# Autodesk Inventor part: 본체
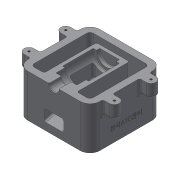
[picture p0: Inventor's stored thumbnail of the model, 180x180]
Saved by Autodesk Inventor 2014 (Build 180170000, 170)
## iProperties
Created: 2018-01
Part Number: 본체
Material: Generic
Document SubType Name: Modeling
Designer: user
Density: 1 g/cm^3
Appearance: Default
Mass: 368.651 g
Surface Area: 834.687 cm^2
Volume: 368.651 cm^3
Author: user
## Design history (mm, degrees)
sketch "Sketch1"
  geometry: L1 (-40, 55)-(40, 55); L2 (55, 40)-(55, -40); L3 (40, -55)-(-40, -55); L4 (-55, -40)-(-55, 40); L5 (40, 45)-(-40, 45); L6 (-45, 40)-(-45, -40); L7 (-40, -45)-(40, -45); L8 (45, -40)-(45, 40); A1 r 15 centre (-40, 40) between (-40, 55) and (-55, 40); A2 r 15 centre (40, 40) between (55, 40) and (40, 55); A3 r 15 centre (40, -40) between (40, -55) and (55, -40); A4 r 15 centre (-40, -40) between (-55, -40) and (-40, -55); A5 r 5 centre (-40, 40) between (-40, 45) and (-45, 40); A6 r 5 centre (40, 40) between (45, 40) and (40, 45); A7 r 5 centre (40, -40) between (40, -45) and (45, -40); A8 r 5 centre (-40, -40) between (-45, -40) and (-40, -45); 1 further point
  constraints: 16 end point, 16 point on circle, 16 tangent, 8 centre point, 6 equal radius, 4 parallel, 2 perpendicular, 1 horizontal, 3 other
  dimensions: "d0" = 110 distance between parallel lines of L3 L1; "d1" = 110 distance between parallel lines of L2 L4; "d2" = 55 distance from line of point (0, 0) L4; "d3" = 55 distance from line of point (0, 0) L1; "d4" = 10 distance between parallel lines of L5 L1; "d5" = 15 radius of A1; "d6" = 5 radius of A5
extrude "Extrusion1" new body sketch "Sketch1" distance "d7" = 65; taper "d8" = 0 deg
sketch "Sketch2"
  geometry: L1 (-65, -35.5)-(-55, -35.5); L2 (-65, -20.5)-(-55, -20.5); L3 (-65, 20.5)-(-55, 20.5); L4 (-65, 35.5)-(-55, 35.5); L5 (-55, 40)-(-55, -40) reference; L6 (-40, -55)-(40, -55) reference; L7 (-55, -35.5)-(-55, -20.5); L8 (-55, 20.5)-(-55, 35.5); A1 r 7.5 centre (-65, -28) between (-65, -20.5) and (-65, -35.5); A2 r 7.5 centre (-65, 28) between (-65, 35.5) and (-65, 20.5); 1 further point
  constraints: 12 end point, 4 point on circle, 4 point on line, 4 tangent, 3 parallel, 2 centre point, 2 collinear, 1 horizontal, 1 vertical alignment
  dimensions: "d9" = 15 diameter of A1; "d10" = 15 diameter of A2; "d11" = 27 distance from line of L6 A1.centre; "d12" = 56 distance of A1.centre A2.centre; "d13" = 10 distance from line of L5 A1.centre
extrude "Extrusion2" join sketch "Sketch2" distance "d14" = 20; taper "d15" = 0 deg
mirror "Mirror1"
sketch "Sketch3"
  geometry: A1 r 7.5 centre (-65, -28) between (-65, -20.5) and (-65, -35.5) reference; A2 r 7.5 centre (-65, 28) between (-65, 35.5) and (-65, 20.5) reference; A3 r 7.5 centre (65, 28) between (65, 20.5) and (65, 35.5) reference; A4 r 7.5 centre (65, -28) between (65, -35.5) and (65, -20.5) reference; 1 further point
hole "Hole1" sketch "Sketch3" at (-65, -28), (-65, 28), (65, 28), (65, -28) diameter "d16" = 3.242; stored, may be unused: countersink angle "d20" = 90 deg, drill point angle "d22" = 118 deg; dims "d17" = 9, "d18" = 4, "d19" = 2, "d21" = 11
sketch "Sketch4"
  geometry: L1 (8.564, 45)-(30, -35); L2 (30, -35)-(65, -35); L3 (0, 45)-(65, 45) reference; L4 (65, 40)-(65, -40) reference; L5 (0, -40)-(0, 40) reference; L6 (0, -55)-(65, -55) reference; L7 (65, -35)-(65, 45); L8 (65, 45)-(8.564, 45); 1 further point
  constraints: 8 end point, 2 collinear, 2 point on line, 1 horizontal
  dimensions: "d23" = 105 deg angle of L3 L1; "d24" = 30 distance from line of L5 L1.end; "d26" = 20 distance between parallel lines of L6 L2
extrude "Extrusion3" join sketch "Sketch4" stored distance "d27" = 50; taper "d28" = 0 deg
sketch "Sketch5"
  geometry: L1 (65, 55)-(65, -30); L2 (65, 45)-(65, -35) reference; L3 (65, 55)-(57.5, 55); L4 (57.5, 55)-(57.5, 36); L5 (57.5, 36)-(49, 36); L6 (49, 36)-(49, 22); L7 (49, 22)-(45, 22); L8 (45, 22)-(45, -25); L9 (45, -25)-(50, -25); L10 (50, -25)-(50, -30); L11 (50, -30)-(65, -30); L12 (0, 55)-(65, 55) reference; 1 further point
  constraints: 20 end point, 7 parallel, 2 collinear, 2 perpendicular, 2 point on line, 1 vertical
  dimensions: "d29" = 7.5 distance of L1.start L3.end; "d30" = 19 distance of L3.end L4.end; "d31" = 14 distance between parallel lines of L7 L5; "d32" = 16 distance between parallel lines of L6 L1; "d33" = 20 distance between parallel lines of L1 L8; "d34" = 47 distance between parallel lines of L9 L7; "d35" = 15 distance between parallel lines of L1 L10; "d36" = 5 distance between parallel lines of L11 L9
revolve "Revolution1" sketch "Sketch5" stored, may be unused: angle "d37" = 90 deg
sketch "Sketch6"
  geometry: L1 (11.061, 55)-(31.157, -20); L2 (31.157, -20)-(65, -20); L3 (65, -20)-(65, 17); L4 (65, 17)-(39.243, 17); L5 (39.243, 17)-(29.061, 55); L6 (30, -35)-(8.564, 45) reference; L7 (0, 55)-(65, 55) reference; L8 (29.061, 55)-(11.061, 55); L9 (45, 22)-(65, 22) reference; L10 (65, 22)-(65, -25) reference; 1 further point
  constraints: 12 end point, 2 collinear, 2 parallel, 2 perpendicular, 2 point on line, 1 horizontal
  dimensions: "d38" = 5 distance between parallel lines of L6 L1; "d39" = 18 distance of L1.start L5.end; "d40" = 37 distance between parallel lines of L2 L4; "d41" = 5 distance between parallel lines of L9 L4
extrude "Extrusion4" cut sketch "Sketch6" stored distance "d42" = 30; taper "d43" = 0 deg
chamfer "Chamfer1" distance "d44" = 1; stored, may be unused: second distance "d45" = 2, angle "d46" = 45 deg
fillet "Fillet4" dims "d50" = 1
fillet "Fillet5" dims "d51" = 3
fillet "Fillet6" dims "d52" = 3
fillet "Fillet7" dims "d53" = 3
sketch "Sketch8"
  geometry: L1 (-15, 0)-(-15, 65) reference; L2 (15.113, 23.602)-(64.887, 23.602); L3 (64.887, 23.602)-(64.887, 16.398); L4 (64.887, 16.398)-(15.113, 16.398); L5 (15.113, 16.398)-(15.113, 23.602); L6 (40, 23.602)-(40, 16.398); L7 (15.113, 20)-(64.887, 20); 1 further point
  constraints: 4 end point, 4 midpoint, 2 other
  dimensions: "d57" = 55 distance between parallel lines of L1 L6; "d58" = 20 distance from line of point (40, 0) L7
emboss "Emboss1" sketch "Sketch8" dims "d0" = 110, "d1" = 110, "d2" = 55, "d3" = 55, "d4" = 10, "d5" = 15, "d6" = 5, "d59" = 0.5, "d60" = 0
body "Solid1"
